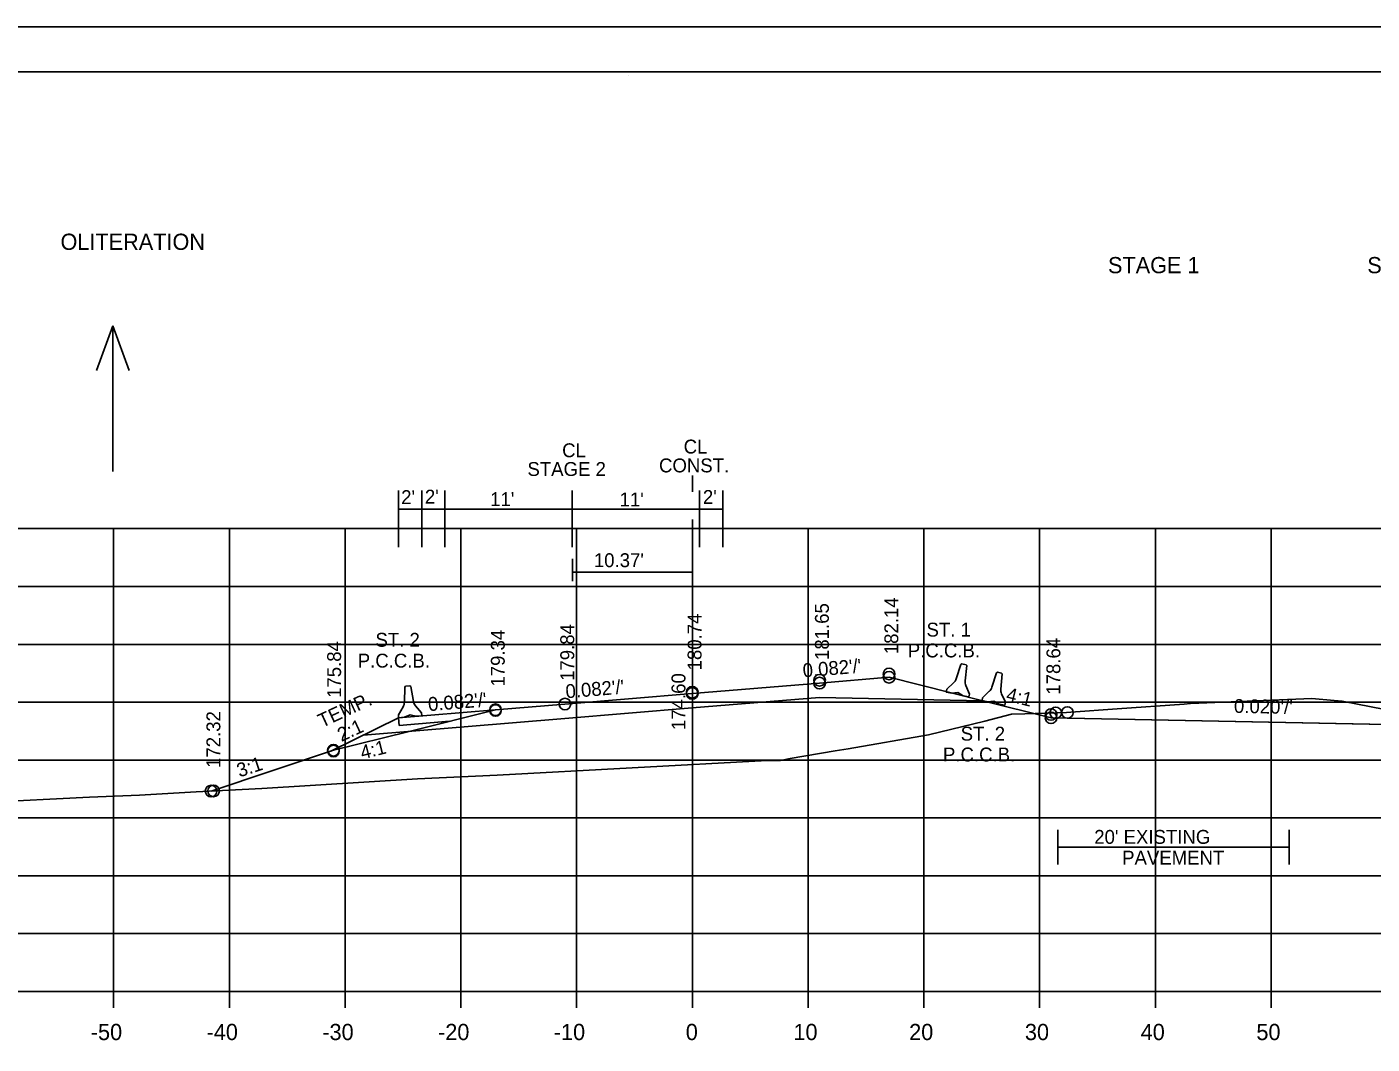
# Model space of a CAD drawing. Extents: x 915787 to 919910, y 133456 to 136717.
# Drawn here: x 916356.5 to 916472.7, y 133794.8 to 133882.7 of the extents above; entities that cross this region are included whole.
import ezdxf

# ---------------------------------------------------------------- set-up
doc = ezdxf.new("R2010")
doc.units = 0
for name, color, linetype in [('R_Axis', 7, 'Continuous'), ('R_Axis Annot', 7, 'Continuous'), ('R_Border', 7, 'Continuous'), ('R_Border Notes', 7, 'Continuous'), ('R_Exist Surface', 7, 'Continuous'), ('R_Exist Surface Annot', 7, 'Continuous'), ('R_Fin Surface', 7, 'Continuous'), ('R_Grid', 7, 'Continuous'), ('R_MOT', 7, 'Continuous'), ('R_No Plot', 7, 'Continuous'), ('R_Water', 7, 'Continuous'), ('R_Water Annot', 7, 'Continuous'), ('R_Xsect Elev', 7, 'Continuous'), ('R_Xsect Slope', 7, 'Continuous')]:
    doc.layers.add(name, color=color, linetype=linetype)

msp = doc.modelspace()

# ---------------------------------------------------------------- linework, layer by layer
at = {"layer": 'R_Axis'}
for p, q in [((916273.98, 133799.35), (916553.98, 133799.35)), ((916363.98, 133797.95), (916363.98, 133799.35)), ((916373.98, 133797.95), (916373.98, 133799.35)), ((916383.98, 133797.95), (916383.98, 133799.35)), ((916393.98, 133797.95), (916393.98, 133799.35)), ((916403.98, 133797.95), (916403.98, 133799.35)), ((916413.98, 133797.95), (916413.98, 133799.35)), ((916423.98, 133797.95), (916423.98, 133799.35)), ((916433.98, 133797.95), (916433.98, 133799.35)), ((916443.98, 133797.95), (916443.98, 133799.35)), ((916453.98, 133797.95), (916453.98, 133799.35)), ((916463.98, 133797.95), (916463.98, 133799.35))]:
    msp.add_line(p, q, dxfattribs=at)
at = {"layer": 'R_Border'}
for p, q in [((916255.98, 133878.81), (916572.16, 133878.81)), ((916408.5, 133878.55), (916408.5, 133878.55)), ((916408.5, 133878.55), (916408.5, 133878.55))]:
    msp.add_line(p, q, dxfattribs=at)
at = {"layer": 'R_Border Notes'}
for p, q in [((916413.98, 133842.54), (916413.98, 133843.94)), ((916413.98, 133834.8), (916413.98, 133840.13)), ((916403.61, 133834.8), (916403.61, 133836.73)), ((916403.61, 133835.59), (916413.98, 133835.59))]:
    msp.add_line(p, q, dxfattribs=at)
at = {"layer": 'R_Exist Surface'}
msp.add_lwpolyline([(916343.6, 133815.22), (916361.89, 133816.13), (916366.21, 133816.32), (916371.1, 133816.61), (916376.78, 133816.89), (916390.23, 133817.72), (916397.13, 133818.04), (916420.45, 133819.3), (916421.6, 133819.32), (916422.42, 133819.47), (916426.31, 133820.14), (916427.45, 133820.33), (916434.37, 133821.54), (916439.25, 133822.71), (916441.55, 133823.31), (916442.69, 133823.33), (916446.31, 133823.46), (916446.69, 133823.48), (916450.68, 133823.77), (916456.48, 133824.19), (916457.03, 133824.23), (916457.73, 133824.26), (916467.5, 133824.66), (916469.42, 133824.5), (916470.11, 133824.44), (916473.8, 133823.73)], dxfattribs=at)
at = {"layer": 'R_Exist Surface Annot'}
for p, q in [((916445.55, 133813.31), (916445.55, 133810.31)), ((916465.54, 133813.31), (916465.54, 133810.31)), ((916445.55, 133811.81), (916465.54, 133811.81))]:
    msp.add_line(p, q, dxfattribs=at)
at = {"layer": 'R_Fin Surface'}
for points in [[(916372.4, 133816.67), (916382.97, 133820.2), (916389.52, 133821.83), (916396.97, 133823.7), (916402.97, 133824.19), (916413.97, 133825.1), (916424.97, 133826), (916430.97, 133826.5), (916439.08, 133824.47), (916444.97, 133823), (916481.22, 133822.27)], [(916385.56, 133821.51), (916402.97, 133822.94), (916413.97, 133823.85), (916424.97, 133824.75), (916439.08, 133824.47)]]:
    msp.add_lwpolyline(points, dxfattribs=at)
at = {"layer": 'R_Grid'}
for p, q in [((916273.98, 133839.35), (916553.98, 133839.35)), ((916363.98, 133799.35), (916363.98, 133839.35)), ((916373.98, 133799.35), (916373.98, 133839.35)), ((916383.98, 133799.35), (916383.98, 133839.35)), ((916393.98, 133799.35), (916393.98, 133839.35)), ((916403.98, 133799.35), (916403.98, 133839.35)), ((916413.98, 133799.35), (916413.98, 133839.35)), ((916423.98, 133799.35), (916423.98, 133839.35)), ((916433.98, 133799.35), (916433.98, 133839.35)), ((916443.98, 133799.35), (916443.98, 133839.35)), ((916453.98, 133799.35), (916453.98, 133839.35)), ((916463.98, 133799.35), (916463.98, 133839.35)), ((916273.98, 133834.35), (916553.98, 133834.35)), ((916273.98, 133829.35), (916553.98, 133829.35)), ((916273.98, 133824.35), (916553.98, 133824.35)), ((916273.98, 133819.35), (916553.98, 133819.35)), ((916273.98, 133814.35), (916553.98, 133814.35)), ((916273.98, 133809.35), (916553.98, 133809.35)), ((916273.98, 133804.35), (916553.98, 133804.35)), ((916273.98, 133799.35), (916553.98, 133799.35))]:
    msp.add_line(p, q, dxfattribs=at)
at = {"layer": 'R_MOT'}
for p, q in [((916437.18, 133827.62), (916436.77, 133826.37)), ((916437.18, 133827.62), (916437.26, 133827.66)), ((916437.26, 133827.66), (916437.63, 133827.58)), ((916437.68, 133827.51), (916437.54, 133826.2)), ((916437.63, 133827.58), (916437.68, 133827.51)), ((916440.25, 133826.89), (916439.85, 133825.64)), ((916440.25, 133826.89), (916440.33, 133826.94)), ((916440.33, 133826.94), (916440.7, 133826.87)), ((916440.75, 133826.79), (916440.63, 133825.49)), ((916440.7, 133826.87), (916440.75, 133826.79)), ((916389.14, 133825.66), (916389.11, 133824.35)), ((916389.14, 133825.66), (916389.2, 133825.73)), ((916389.2, 133825.73), (916389.58, 133825.76)), ((916389.58, 133825.76), (916389.65, 133825.7)), ((916389.65, 133825.7), (916389.89, 133824.41)), ((916435.96, 133825.47), (916435.91, 133825.23)), ((916436.39, 133825.12), (916435.91, 133825.23)), ((916436.55, 133826.02), (916435.96, 133825.47)), ((916436.39, 133825.12), (916436.92, 133825.18)), ((916436.92, 133825.18), (916437.37, 133824.91)), ((916437.6, 133825.79), (916437.91, 133825.05)), ((916437.91, 133825.05), (916437.86, 133824.81)), ((916439.63, 133825.29), (916439.05, 133824.73)), ((916440.69, 133825.07), (916441.02, 133824.34)), ((916388.99, 133823.95), (916388.59, 133823.26)), ((916390.07, 133824.03), (916390.58, 133823.42)), ((916437.37, 133824.91), (916437.86, 133824.81)), ((916439.05, 133824.73), (916439.01, 133824.49)), ((916439.5, 133824.39), (916439.01, 133824.49)), ((916439.5, 133824.39), (916440.02, 133824.45)), ((916440.02, 133824.45), (916440.48, 133824.19)), ((916440.48, 133824.19), (916440.97, 133824.09)), ((916441.02, 133824.34), (916440.97, 133824.09)), ((916388.59, 133823.26), (916388.6, 133823.01)), ((916389.1, 133823.05), (916388.6, 133823.01)), ((916389.1, 133823.05), (916389.59, 133823.25)), ((916389.59, 133823.25), (916390.1, 133823.13)), ((916390.1, 133823.13), (916390.6, 133823.17)), ((916390.58, 133823.42), (916390.6, 133823.17))]:
    msp.add_line(p, q, dxfattribs=at)
for centre, start, end in [((916435.98, 133826.63), 312.8834, 341.8664), ((916438.37, 133826.11), 173.8844, 202.8674), ((916439.06, 133825.89), 313.6404, 342.6235), ((916441.46, 133825.41), 174.6415, 203.6245), ((916388.27, 133824.37), 329.5753, 358.5583), ((916390.71, 133824.56), 190.5763, 219.5593)]:
    msp.add_arc(centre, 0.833, start, end, dxfattribs=at)
at = {"layer": 'R_No Plot'}
msp.add_line((916243.57, 133882.71), (916576.91, 133882.71), dxfattribs=at)
for points in [[(916243.57, 133882.71), (916576.91, 133882.71), (916576.91, 133669.37), (916243.57, 133669.37)], [(916489.9, 133878.81), (916489.9, 133868.93), (916525.63, 133868.93), (916525.63, 133866.01), (916548.83, 133866.01), (916548.83, 133842.8), (916572.16, 133842.8), (916572.16, 133673.35), (916255.98, 133673.35), (916255.98, 133878.81)]]:
    msp.add_lwpolyline(points, close=True, dxfattribs=at)
for centre in [(916424.97, 133826.24), (916424.97, 133826), (916430.97, 133826.79), (916430.97, 133826.5), (916413.97, 133825.21), (916413.97, 133825.1), (916396.97, 133823.7), (916396.97, 133823.63), (916402.97, 133824.19), (916402.97, 133824.19), (916445.37, 133823.43), (916445.37, 133823.43), (916446.38, 133823.46), (916444.97, 133823.29), (916444.97, 133823), (916382.97, 133820.2), (916382.97, 133820.13), (916372.4, 133816.67), (916372.62, 133816.68)]:
    msp.add_circle(centre, 0.5, dxfattribs=at)
at = {"layer": 'R_Water'}
msp.add_line((916444.97, 133823), (916479.54, 133822.3), dxfattribs=at)
at = {"layer": 'R_Water Annot'}
for p, q in [((916363.91, 133856.86), (916362.51, 133853.01)), ((916363.91, 133844.29), (916363.91, 133856.86)), ((916363.91, 133856.86), (916365.31, 133853.01))]:
    msp.add_line(p, q, dxfattribs=at)
at = {"layer": 'R_Xsect Slope'}
for p, q in [((916388.6, 133837.74), (916388.6, 133842.65)), ((916390.6, 133837.74), (916390.6, 133842.65)), ((916392.6, 133837.74), (916392.6, 133842.65)), ((916403.6, 133837.74), (916403.6, 133842.65)), ((916414.6, 133837.74), (916414.6, 133842.65)), ((916416.6, 133837.74), (916416.6, 133842.65)), ((916388.6, 133841.03), (916416.6, 133841.03)), ((916388.6, 133823.01), (916382.74, 133820.12)), ((916396.97, 133823.7), (916388.6, 133823.01))]:
    msp.add_line(p, q, dxfattribs=at)
msp.add_lwpolyline([(916392.99, 133822.7), (916388.66, 133822.34), (916388.6, 133823.01)], dxfattribs=at)

# ---------------------------------------------------------------- texts
at = {"layer": 'R_Axis Annot'}
for s, p in [('-50', (916362.01, 133795.15)), ('-40', (916372.01, 133795.15)), ('-30', (916382.01, 133795.15)), ('-20', (916392.01, 133795.15)), ('-10', (916402.01, 133795.15)), ('0', (916413.41, 133795.15)), ('10', (916422.71, 133795.15)), ('20', (916432.71, 133795.15)), ('30', (916442.71, 133795.15)), ('40', (916452.71, 133795.15)), ('50', (916462.71, 133795.15))]:
    msp.add_text(s, height=1.4, dxfattribs=at).set_placement(p)
at = {"layer": 'R_Border Notes'}
for s, height, p in [('OLITERATION', 1.4, (916359.39, 133863.44)), ('STAGE 1', 1.4, (916449.89, 133861.42)), ('STAGE 2', 1.4, (916472.29, 133861.42)), ('CL', 1.2, (916402.73, 133845.52)), ('CL', 1.2, (916413.23, 133845.84)), ('STAGE 2', 1.2, (916399.73, 133843.9)), ('CONST.', 1.2, (916411.1, 133844.21)), ("10.37'", 1.2, (916405.47, 133836.02))]:
    msp.add_text(s, height=height, dxfattribs=at).set_placement(p)
at = {"layer": 'R_Exist Surface Annot'}
for s, p in [("20' EXISTING", (916448.7, 133812.11)), ('PAVEMENT', (916451.11, 133810.31))]:
    msp.add_text(s, height=1.2, dxfattribs=at).set_placement(p)
at = {"layer": 'R_MOT'}
for rotation, p in [(77.8754, (916435.91, 133825.23)), (78.6325, (916439.01, 133824.49)), (94.5673, (916388.61, 133823.01))]:
    msp.add_text('DWB 1-14-10', height=0.004, rotation=rotation, dxfattribs=at).set_placement(p)
at = {"layer": 'R_Xsect Elev'}
for s, p in [('182.14', (916431.77, 133828.5)), ('180.74', (916414.77, 133827.1)), ('181.65', (916425.77, 133828)), ('179.84', (916403.77, 133826.19)), ('179.34', (916397.77, 133825.7)), ('178.64', (916445.77, 133825)), ('175.84', (916383.63, 133824.72)), ('174.60', (916413.38, 133821.95)), ('172.32', (916373.2, 133818.67))]:
    msp.add_text(s, height=1.2, rotation=90, dxfattribs=at).set_placement(p)
at = {"layer": 'R_Xsect Slope'}
for s, p in [("2'", (916388.82, 133841.47)), ("2'", (916390.87, 133841.51)), ("11'", (916396.51, 133841.3)), ("11'", (916407.69, 133841.27)), ("2'", (916414.89, 133841.48)), ('ST. 1', (916434.21, 133830.02)), ('ST. 2', (916386.6, 133829.14)), ('P.C.C.B.', (916385.07, 133827.34)), ('P.C.C.B.', (916432.59, 133828.22)), ('ST. 2', (916437.16, 133821.03)), ('P.C.C.B.', (916435.63, 133819.23))]:
    msp.add_text(s, height=1.2, dxfattribs=at).set_placement(p)
for s, rotation, p in [("0.082'/'", 4.7074, (916423.56, 133826.49)), ("0.082'/'", 4.7074, (916403.07, 133824.68)), ("0.082'/'", 4.7074, (916391.19, 133823.57)), ('4:1', 345.9638, (916441.01, 133824.49)), ('TEMP.', 24.829, (916381.98, 133822.12)), ("0.020'/'", 358.8542, (916460.76, 133823.43)), ('2:1', 24.829, (916383.66, 133820.91)), ('4:1', 14.0362, (916385.46, 133819.4)), ('3:1', 18.4349, (916374.85, 133817.84))]:
    msp.add_text(s, height=1.2, rotation=rotation, dxfattribs=at).set_placement(p)

doc.saveas('drawing.dxf')
